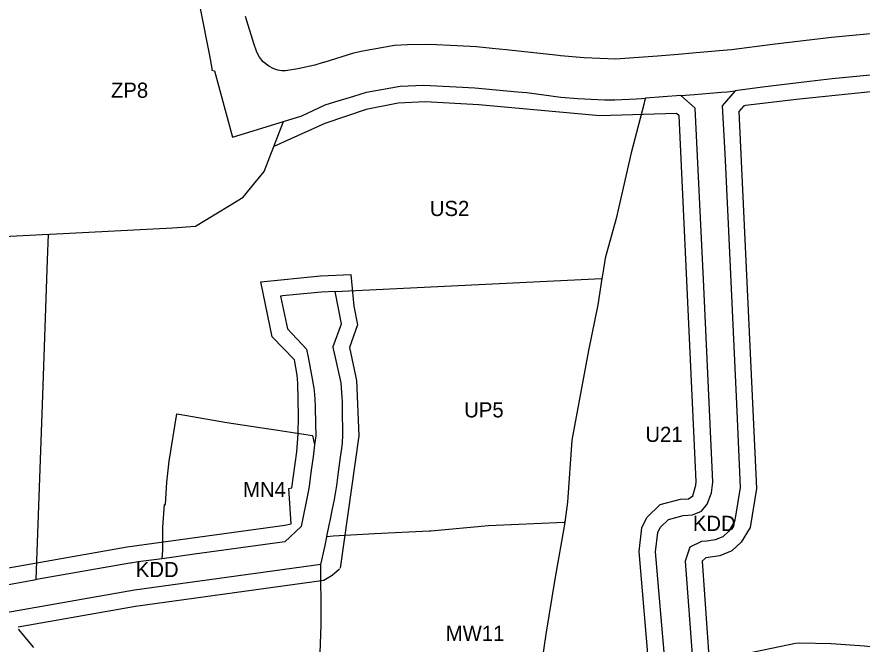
# Model space of a CAD drawing. Extents: x 7428103 to 7431580, y 5545880 to 5549002.
# Drawn here: x 7429340.3 to 7429649.7, y 5548058.7 to 5548288 of the extents above; entities that cross this region are included whole.
import ezdxf

# ---------------------------------------------------------------- set-up
doc = ezdxf.new("R2010")
doc.units = 0
for name, color, linetype in [('CZ_L_linie rozgraniczające tereny o różnym przeznaczeniu oraz różnych warunkach ich zabudowy i zagospodarowania', 7, 'Continuous'), ('CZ_L_maksymalne nieprzekraczalne linie zabudowy', 7, 'Continuous'), ('CZ_L_opisy_linie rozgraniczające tereny o różnym przeznaczeniu oraz różnych warunkach ich zabudowy i zagospodarowania', 7, 'Continuous')]:
    doc.layers.add(name, color=color, linetype=linetype)

msp = doc.modelspace()

# ---------------------------------------------------------------- linework, layer by layer
at = {"layer": 'CZ_L_linie rozgraniczające tereny o różnym przeznaczeniu oraz różnych warunkach ich zabudowy i zagospodarowania'}
for p, q in [((7429407.37, 5548291.1), (7429410.76, 5548273.99)), ((7429426.99, 5548278.37), (7429423.96, 5548288.2)), ((7429638.47, 5548280.52), (7429616.89, 5548277.92)), ((7429655.33, 5548282.07), (7429638.47, 5548280.52)), ((7429428.2, 5548275.1), (7429426.99, 5548278.37)), ((7429478.49, 5548277.59), (7429466.93, 5548275.56)), ((7429483.31, 5548277.85), (7429478.49, 5548277.59)), ((7429491.4, 5548278), (7429483.31, 5548277.85)), ((7429501.41, 5548277.47), (7429491.4, 5548278)), ((7429508.6, 5548277.09), (7429501.41, 5548277.47)), ((7429514.25, 5548276.54), (7429508.6, 5548277.09)), ((7429519.39, 5548275.99), (7429514.25, 5548276.54)), ((7429616.89, 5548277.92), (7429601.9, 5548276.01)), ((7429410.76, 5548273.99), (7429411.73, 5548269.22)), ((7429429.1, 5548273.3), (7429428.2, 5548275.1)), ((7429430.43, 5548271.66), (7429429.1, 5548273.3)), ((7429463.57, 5548274.82), (7429452.62, 5548271.36)), ((7429466.93, 5548275.56), (7429463.57, 5548274.82)), ((7429538.51, 5548273.95), (7429519.39, 5548275.99)), ((7429539.31, 5548273.87), (7429538.51, 5548273.95)), ((7429547.96, 5548273.14), (7429539.31, 5548273.87)), ((7429559.45, 5548272.63), (7429547.96, 5548273.14)), ((7429574.82, 5548273.67), (7429559.45, 5548272.63)), ((7429582.32, 5548274.25), (7429574.82, 5548273.67)), ((7429587.59, 5548274.73), (7429582.32, 5548274.25)), ((7429597.41, 5548275.61), (7429587.59, 5548274.73)), ((7429601.9, 5548276.01), (7429597.41, 5548275.61)), ((7429432.56, 5548270.08), (7429430.43, 5548271.66)), ((7429434.36, 5548269.12), (7429432.56, 5548270.08)), ((7429449.41, 5548270.43), (7429443.11, 5548269.08)), ((7429452.39, 5548271.32), (7429449.41, 5548270.43)), ((7429452.62, 5548271.36), (7429452.39, 5548271.32)), ((7429411.73, 5548269.22), (7429411.73, 5548268.56)), ((7429411.73, 5548268.56), (7429412.69, 5548268.32)), ((7429412.69, 5548268.32), (7429419.25, 5548244.08)), ((7429435.84, 5548268.52), (7429434.36, 5548269.12)), ((7429437.3, 5548268.35), (7429435.84, 5548268.52)), ((7429438.67, 5548268.38), (7429437.3, 5548268.35)), ((7429443.11, 5548269.08), (7429438.67, 5548268.38)), ((7429630.45, 5548264.45), (7429613.24, 5548262.35)), ((7429638.77, 5548265.45), (7429630.45, 5548264.45)), ((7429652.63, 5548266.79), (7429638.77, 5548265.45)), ((7429468.23, 5548260.56), (7429480.59, 5548262.73)), ((7429480.59, 5548262.73), (7429489.33, 5548263.08)), ((7429489.33, 5548263.08), (7429501.16, 5548262.47)), ((7429501.16, 5548262.47), (7429507.94, 5548262.09)), ((7429507.94, 5548262.09), (7429523.56, 5548260.66)), ((7429603.28, 5548261.06), (7429598.49, 5548255.54)), ((7429600.34, 5548260.68), (7429603.28, 5548261.06)), ((7429613.24, 5548262.35), (7429603.28, 5548261.06)), ((7429456.68, 5548256.94), (7429463.6, 5548259.11)), ((7429463.6, 5548259.11), (7429468.23, 5548260.56)), ((7429523.56, 5548260.66), (7429526.92, 5548260.43)), ((7429526.92, 5548260.43), (7429539.44, 5548258.67)), ((7429539.44, 5548258.67), (7429545.59, 5548258.24)), ((7429545.59, 5548258.24), (7429555.42, 5548257.75)), ((7429555.42, 5548257.75), (7429559.23, 5548257.73)), ((7429559.23, 5548257.73), (7429566.99, 5548258.09)), ((7429566.99, 5548258.09), (7429568.93, 5548258.22)), ((7429568.93, 5548258.22), (7429570.35, 5548258.33)), ((7429570.35, 5548258.33), (7429570.08, 5548257.19)), ((7429583.34, 5548259.32), (7429570.35, 5548258.33)), ((7429583.34, 5548259.32), (7429588.32, 5548259.7)), ((7429588.57, 5548254.7), (7429583.34, 5548259.32)), ((7429588.32, 5548259.7), (7429593.9, 5548260.12)), ((7429593.9, 5548260.12), (7429598.22, 5548260.5)), ((7429598.22, 5548260.5), (7429600.34, 5548260.68)), ((7429444.61, 5548251.86), (7429453.16, 5548255.84)), ((7429453.16, 5548255.84), (7429456.68, 5548256.94)), ((7429569.8, 5548255.97), (7429565.15, 5548238.4)), ((7429570.08, 5548257.19), (7429569.8, 5548255.97)), ((7429591.66, 5548192.02), (7429588.57, 5548254.7)), ((7429598.49, 5548255.54), (7429599.43, 5548238.05)), ((7429437.87, 5548249.79), (7429444.61, 5548251.86)), ((7429419.25, 5548244.08), (7429437.87, 5548249.79)), ((7429430.87, 5548231.55), (7429437.87, 5548249.79)), ((7429565.15, 5548238.4), (7429559.65, 5548214.35)), ((7429599.43, 5548238.05), (7429600.68, 5548212.34)), ((7429425.88, 5548225.45), (7429430.87, 5548231.55)), ((7429423.13, 5548222.08), (7429425.88, 5548225.45)), ((7429417.83, 5548218.87), (7429423.13, 5548222.08)), ((7429405.71, 5548211.51), (7429417.83, 5548218.87)), ((7429559.65, 5548214.35), (7429555.66, 5548199.89)), ((7429397.24, 5548210.92), (7429405.71, 5548211.51)), ((7429600.68, 5548212.34), (7429603.78, 5548143.9)), ((7429351.88, 5548208.53), (7429323.27, 5548206.99)), ((7429351.56, 5548199.19), (7429351.88, 5548208.53)), ((7429351.88, 5548208.53), (7429352.54, 5548208.57)), ((7429352.54, 5548208.57), (7429397.24, 5548210.92)), ((7429349.84, 5548149.76), (7429351.56, 5548199.19)), ((7429555.66, 5548199.89), (7429554.77, 5548194.36)), ((7429554.77, 5548194.36), (7429554.48, 5548192.45)), ((7429456.81, 5548187.64), (7429554.47, 5548192.45)), ((7429554.48, 5548192.45), (7429552.99, 5548182.75)), ((7429554.47, 5548192.45), (7429554.48, 5548192.45)), ((7429595, 5548118.02), (7429591.66, 5548192.02)), ((7429442.69, 5548186.52), (7429437.72, 5548186.02)), ((7429451.82, 5548187.39), (7429442.69, 5548186.52)), ((7429456.81, 5548187.64), (7429451.82, 5548187.39)), ((7429459.11, 5548175.86), (7429456.81, 5548187.64)), ((7429437.72, 5548186.02), (7429436.83, 5548185.93)), ((7429436.83, 5548185.93), (7429439.32, 5548174.01)), ((7429552.99, 5548182.75), (7429549.55, 5548166.13)), ((7429456.09, 5548167.55), (7429459.11, 5548175.86)), ((7429439.32, 5548174.01), (7429446.34, 5548166.61)), ((7429446.34, 5548166.61), (7429446.88, 5548163.66)), ((7429456.26, 5548166.73), (7429456.09, 5548167.55)), ((7429456.97, 5548163.45), (7429456.26, 5548166.73)), ((7429549.55, 5548166.13), (7429543.48, 5548133.24)), ((7429446.88, 5548163.66), (7429448.11, 5548157.05)), ((7429458.96, 5548154.2), (7429456.97, 5548163.45)), ((7429448.11, 5548157.05), (7429448.99, 5548152.3)), ((7429459.41, 5548148.99), (7429458.96, 5548154.2)), ((7429347.33, 5548082.28), (7429349.84, 5548149.76)), ((7429448.99, 5548152.3), (7429449.16, 5548151.37)), ((7429449.16, 5548151.37), (7429449.42, 5548148.35)), ((7429449.42, 5548148.35), (7429449.48, 5548145.5)), ((7429459.44, 5548147.26), (7429459.41, 5548148.99)), ((7429459.55, 5548141.78), (7429459.44, 5548147.26)), ((7429449.48, 5548145.5), (7429449.6, 5548139.23)), ((7429603.78, 5548143.9), (7429605.02, 5548116)), ((7429396.09, 5548125.63), (7429398.89, 5548142.97)), ((7429398.89, 5548142.97), (7429399.7, 5548142.85)), ((7429399.7, 5548142.85), (7429399.71, 5548142.82)), ((7429399.71, 5548142.82), (7429417.15, 5548139.71)), ((7429459.63, 5548138.05), (7429459.55, 5548141.78)), ((7429417.15, 5548139.71), (7429432.5, 5548137.43)), ((7429432.5, 5548137.43), (7429434.28, 5548137.16)), ((7429434.28, 5548137.16), (7429448.56, 5548134.95)), ((7429449.6, 5548139.23), (7429449.69, 5548134.87)), ((7429459.68, 5548135.07), (7429459.63, 5548138.05)), ((7429448.56, 5548134.95), (7429449.26, 5548131.55)), ((7429449.69, 5548134.87), (7429449.37, 5548132.41)), ((7429459.46, 5548132.29), (7429459.68, 5548135.07)), ((7429449.26, 5548131.55), (7429448.71, 5548127.22)), ((7429449.37, 5548132.41), (7429449.26, 5548131.55)), ((7429459.23, 5548130.27), (7429459.46, 5548132.29)), ((7429543.48, 5548133.24), (7429541.87, 5548110.67)), ((7429458.82, 5548127.12), (7429459.23, 5548130.27)), ((7429395.18, 5548117.92), (7429396.09, 5548125.63)), ((7429448.71, 5548127.22), (7429448.18, 5548123.11)), ((7429458.09, 5548121.56), (7429458.82, 5548127.12)), ((7429448.18, 5548123.11), (7429447.59, 5548118.53)), ((7429457.45, 5548116.74), (7429458.09, 5548121.56)), ((7429447.59, 5548118.53), (7429447.32, 5548116.34)), ((7429394.69, 5548109.73), (7429395.18, 5548117.92)), ((7429447.32, 5548116.34), (7429446.79, 5548113.79)), ((7429456.55, 5548111.61), (7429457.45, 5548116.74)), ((7429594.52, 5548113.99), (7429595, 5548117.98)), ((7429595, 5548117.98), (7429595, 5548118.02)), ((7429605.02, 5548116), (7429603.32, 5548105.53)), ((7429446.79, 5548113.79), (7429444.33, 5548101.77)), ((7429593.03, 5548109.84), (7429594.52, 5548113.99)), ((7429393.74, 5548101.51), (7429394.4, 5548109.7)), ((7429394.4, 5548109.7), (7429394.69, 5548109.73)), ((7429455.85, 5548108.16), (7429456.55, 5548111.61)), ((7429541.87, 5548110.67), (7429540.88, 5548103.25)), ((7429590.92, 5548107.38), (7429593.03, 5548109.84)), ((7429454.96, 5548103.78), (7429455.85, 5548108.16)), ((7429587.55, 5548105.96), (7429590.92, 5548107.38)), ((7429454.78, 5548102.86), (7429454.96, 5548103.78)), ((7429540.65, 5548103.14), (7429512.94, 5548102.02)), ((7429540.66, 5548103.24), (7429540.65, 5548103.14)), ((7429540.88, 5548103.25), (7429540.66, 5548103.24)), ((7429540.88, 5548103.25), (7429540.78, 5548102.46)), ((7429575.83, 5548101.38), (7429578.87, 5548104.31)), ((7429578.87, 5548104.31), (7429584.17, 5548105.74)), ((7429584.17, 5548105.74), (7429587.55, 5548105.96)), ((7429602.99, 5548103.52), (7429600.78, 5548099.88)), ((7429603.32, 5548105.53), (7429602.99, 5548103.52)), ((7429393.69, 5548093.1), (7429393.74, 5548101.51)), ((7429444.33, 5548101.77), (7429438.4, 5548096.1)), ((7429453.82, 5548098.12), (7429454.78, 5548102.86)), ((7429491.32, 5548100.03), (7429471.24, 5548099.04)), ((7429491.38, 5548100.01), (7429491.32, 5548100.03)), ((7429491.39, 5548100), (7429491.38, 5548100.01)), ((7429491.46, 5548100.01), (7429491.39, 5548100)), ((7429491.62, 5548100.02), (7429491.46, 5548100.01)), ((7429491.8, 5548100.04), (7429491.62, 5548100.02)), ((7429512.94, 5548102.02), (7429491.8, 5548100.04)), ((7429540.78, 5548102.46), (7429537.22, 5548082.49)), ((7429574.93, 5548099.54), (7429575.83, 5548101.38)), ((7429600.78, 5548099.88), (7429598.72, 5548097.98)), ((7429453.19, 5548094.79), (7429453.79, 5548097.99)), ((7429456.12, 5548098.13), (7429453.79, 5548097.99)), ((7429453.79, 5548097.99), (7429453.82, 5548098.12)), ((7429471.24, 5548099.04), (7429456.12, 5548098.13)), ((7429574.06, 5548092.42), (7429574.93, 5548099.54)), ((7429595.96, 5548096.82), (7429592.89, 5548096.3)), ((7429598.72, 5548097.98), (7429595.96, 5548096.82)), ((7429438.4, 5548096.1), (7429405.3, 5548091.57)), ((7429451.53, 5548087.81), (7429453.19, 5548094.79)), ((7429586.57, 5548094.1), (7429584.88, 5548089.06)), ((7429590.94, 5548096.17), (7429586.57, 5548094.1)), ((7429592.89, 5548096.3), (7429590.94, 5548096.17)), ((7429393.5, 5548089.95), (7429393.69, 5548093.1)), ((7429405.3, 5548091.57), (7429393.5, 5548089.95)), ((7429578.02, 5548046.38), (7429574.06, 5548092.42)), ((7429381.69, 5548088.33), (7429347.45, 5548082.31)), ((7429381.74, 5548088.34), (7429381.69, 5548088.33)), ((7429381.79, 5548088.34), (7429381.74, 5548088.34)), ((7429381.82, 5548088.35), (7429381.79, 5548088.34)), ((7429381.85, 5548088.35), (7429381.82, 5548088.35)), ((7429381.87, 5548088.36), (7429381.85, 5548088.35)), ((7429384.75, 5548088.75), (7429381.87, 5548088.36)), ((7429451.53, 5548087.81), (7429383.33, 5548078.47)), ((7429393.5, 5548089.95), (7429384.75, 5548088.75)), ((7429451.51, 5548083.64), (7429451.53, 5548087.81)), ((7429584.88, 5548089.06), (7429587.91, 5548048.88)), ((7429327.62, 5548078.82), (7429347.33, 5548082.28)), ((7429347.45, 5548082.31), (7429347.33, 5548082.28)), ((7429451.58, 5548079.6), (7429451.51, 5548083.64)), ((7429537.22, 5548082.49), (7429533.91, 5548062.3)), ((7429383.33, 5548078.47), (7429334.25, 5548069.83)), ((7429451.64, 5548076.45), (7429451.58, 5548079.6)), ((7429451.7, 5548073.18), (7429451.64, 5548076.45)), ((7429451.66, 5548065.75), (7429451.7, 5548073.18)), ((7429451.24, 5548052), (7429451.66, 5548065.75)), ((7429533.91, 5548062.3), (7429530.58, 5548039.93))]:
    msp.add_line(p, q, dxfattribs=at)
at = {"layer": 'CZ_L_maksymalne nieprzekraczalne linie zabudowy'}
for points in [[(7429737.56, 5548266.68), (7429712.6, 5548265.77), (7429657.63, 5548261.19), (7429626.79, 5548257.94), (7429606.97, 5548255.66), (7429606.31, 5548255.44), (7429604.61, 5548253.44), (7429611.04, 5548115.65), (7429608.73, 5548101.41), (7429605.47, 5548096.04), (7429602.01, 5548092.86), (7429597.64, 5548091.02), (7429592.48, 5548090.26), (7429591.2, 5548089.04), (7429593.66, 5548052.51), (7429625.28, 5548059.08), (7429626.81, 5548059.19), (7429638.42, 5548058.91), (7429650.51, 5548058.04), (7429686.57, 5548053.92), (7429706.66, 5548051.95), (7429717.21, 5548051.09), (7429737.76, 5548049.93)], [(7429571.86, 5548048), (7429568.03, 5548092.53), (7429569.1, 5548101.27), (7429570.9, 5548104.97), (7429575.82, 5548109.71), (7429583.18, 5548111.68), (7429586.15, 5548111.88), (7429587.76, 5548112.91), (7429588.82, 5548116.79), (7429588.99, 5548118.21), (7429582.7, 5548251.88), (7429581.73, 5548252.67), (7429553.65, 5548251.83), (7429509.35, 5548255.91), (7429489.8, 5548257.05), (7429479.85, 5548256.5), (7429468.13, 5548254.22), (7429453.03, 5548249.09), (7429434.32, 5548240.68)], [(7429328.8, 5548085.12), (7429380.66, 5548094.24), (7429438.34, 5548102.15), (7429440.75, 5548102.71), (7429439.83, 5548115.55), (7429440.9, 5548115.81), (7429442.78, 5548129.03), (7429443.29, 5548135.63), (7429443.42, 5548142.17), (7429443.18, 5548154.1), (7429442.93, 5548157.11), (7429441.89, 5548162.69), (7429433.8, 5548171.11), (7429429.59, 5548191.22), (7429451.39, 5548193.38), (7429462.49, 5548193.83), (7429463.7, 5548182.24), (7429465.04, 5548175.4), (7429462.03, 5548167.14), (7429464.63, 5548155.06), (7429465.42, 5548134.9), (7429458.61, 5548086.44)], [(7429458.35, 5548086.12), (7429455.7, 5548083.8), (7429452.62, 5548082), (7429383.7, 5548072.44), (7429340.73, 5548064.88)], [(7429340.85, 5548064.2), (7429346.35, 5548057.51)]]:
    msp.add_lwpolyline(points, dxfattribs=at)

# ---------------------------------------------------------------- texts
at = {"layer": 'CZ_L_opisy_linie rozgraniczające tereny o różnym przeznaczeniu oraz różnych warunkach ich zabudowy i zagospodarowania'}
for s, p in [('ZP8', (7429374.76, 5548258.47)), ('US2', (7429491.47, 5548215.24)), ('UP5', (7429504.04, 5548141.6)), ('U21', (7429570.37, 5548132.63)), ('MN4', (7429423.12, 5548112.49)), ('KDD', (7429587.74, 5548100.09)), ('KDD', (7429383.85, 5548083.21)), ('MW11', (7429497.31, 5548059.9))]:
    msp.add_text(s, height=5.549, dxfattribs=at).set_placement(p)

doc.saveas('drawing.dxf')
